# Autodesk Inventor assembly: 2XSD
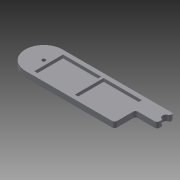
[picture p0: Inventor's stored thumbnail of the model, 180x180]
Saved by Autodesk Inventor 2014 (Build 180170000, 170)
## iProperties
Created: 2015-01
Part Number: 2XSD
Document SubType Name: Assembly
Designer: Drano
Author: Drano
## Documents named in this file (3)
- C:\Users\Drano\Documents\SD swiss army\2XSD.iam
- C:\Users\Drano\Documents\SD swiss army\2XSD.ipt
- C:\Users\Drano\Documents\SD swiss army\backplate.ipt
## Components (2 placed, 2 different names)
1. 2XSD:1 — Mate:1, Mate:2, Flush:1
2. backplate:1 — Mate:1, Mate:2, Flush:1
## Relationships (3: Mate 2, Flush 1)
- Mate:1: 2XSD:1 ↔ backplate:1
- Mate:2: 2XSD:1 ↔ backplate:1
- Flush:1: 2XSD:1 ↔ backplate:1
